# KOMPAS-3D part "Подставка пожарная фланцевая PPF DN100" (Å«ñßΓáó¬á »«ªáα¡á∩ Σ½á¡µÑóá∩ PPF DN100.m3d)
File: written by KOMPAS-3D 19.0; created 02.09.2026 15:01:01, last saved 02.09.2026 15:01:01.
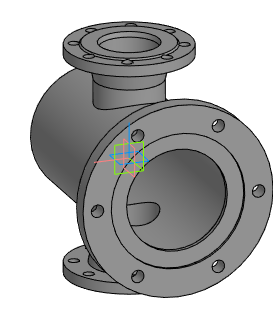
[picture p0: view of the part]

Document properties: Автор: Энергия; Полное имя файла: Z:\3.Личные\sachek\Dendor\_3D для проектировщиков\11.5 Подставка пожарная фланцевая PPF\stp\Подставка пожарная фланцевая PPF DN100.m3d

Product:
- Part/product: Подставка пожарная фланцевая PPF DN100

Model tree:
1. Операция без истории:1  (labels: Подставка пожарная фланцевая PPF DN100)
